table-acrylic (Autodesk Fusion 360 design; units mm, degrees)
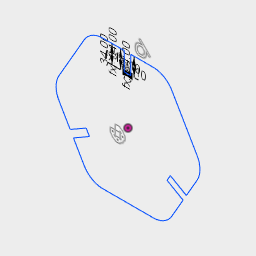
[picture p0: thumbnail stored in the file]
parameter "SlotL" = 34
parameter "SlotW" = 12.1
sketch "lower-acrylic"
  line L1 (80.829, -100) -> (101.3235, -64.5026)
  line L2 (-46.188, -120) -> (46.188, -120)
  line L3 (127.0171, 20) -> (80.829, 100)
  line L4 (107.4232, -53.9376) -> (127.0171, -20)
  line L5 (89.4312, -43.5503) -> (107.4232, -53.9376)
  line L6 (-100.4229, -66.0624) -> (-80.829, -100)
  line L7 (-80.829, 100) -> (-127.0171, 20)
  line L8 (-82.4313, -55.6746) -> (-100.4229, -66.0624)
  line L9 (-127.0171, -20) -> (-106.5226, -55.4974)
  line L10 (-7.0002, 120) -> (-46.188, 120)
  line L11 (-7.0002, 86) -> (-7.0002, 120)
  line L12 (5.0998, 86) -> (-7.0002, 86)
  line L13 (5.0998, 120) -> (5.0998, 86)
  line L14 (46.188, 120) -> (5.0998, 120)
  line L15 (-106.4729, -55.5835) -> (-77.0281, -38.5835)
  line L16 (-77.0281, -38.5835) -> (-70.9781, -49.0624)
  line L17 (-70.9781, -49.0624) -> (-100.4229, -66.0624)
  line L18 (101.3732, -64.4165) -> (71.9283, -47.4165)
  line L19 (71.9283, -47.4165) -> (77.9783, -36.9376)
  line L20 (77.9783, -36.9376) -> (107.4232, -53.9376)
  arc A1 centre (46.188, -80) radius 40 between (46.188, -120) and (80.829, -100)
  arc A2 centre (-46.188, -80) radius 40 between (-80.829, -100) and (-46.188, -120)
  arc A3 centre (46.188, 80) radius 40 between (80.829, 100) and (46.188, 120)
  arc A4 centre (92.376, 0) radius 40 between (127.0171, -20) and (127.0171, 20)
  arc A5 centre (-46.188, 80) radius 40 between (-46.188, 120) and (-80.829, 100)
  arc A6 centre (-92.376, 0) radius 40 between (-127.0171, 20) and (-127.0171, -20)
  point P25 (-7.0002, 120)
  point P27 (-7.0002, 86)
  point P28 (5.0998, 86)
  point P29 (5.0998, 120)
  dimension "d1" distance P25 P27 = 34
  dimension "d2" distance P27 P28 = 12.1
  dimension "d5" distance P28 P29 = 34 (= "SlotL")
  dimension "d6" distance P27 P28 = 12.1 (= "SlotW")
  dimension "d7" distance P25 P27 = 34 (= "SlotL")
  dimension "d10" C-Pattern1-Angle = 360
